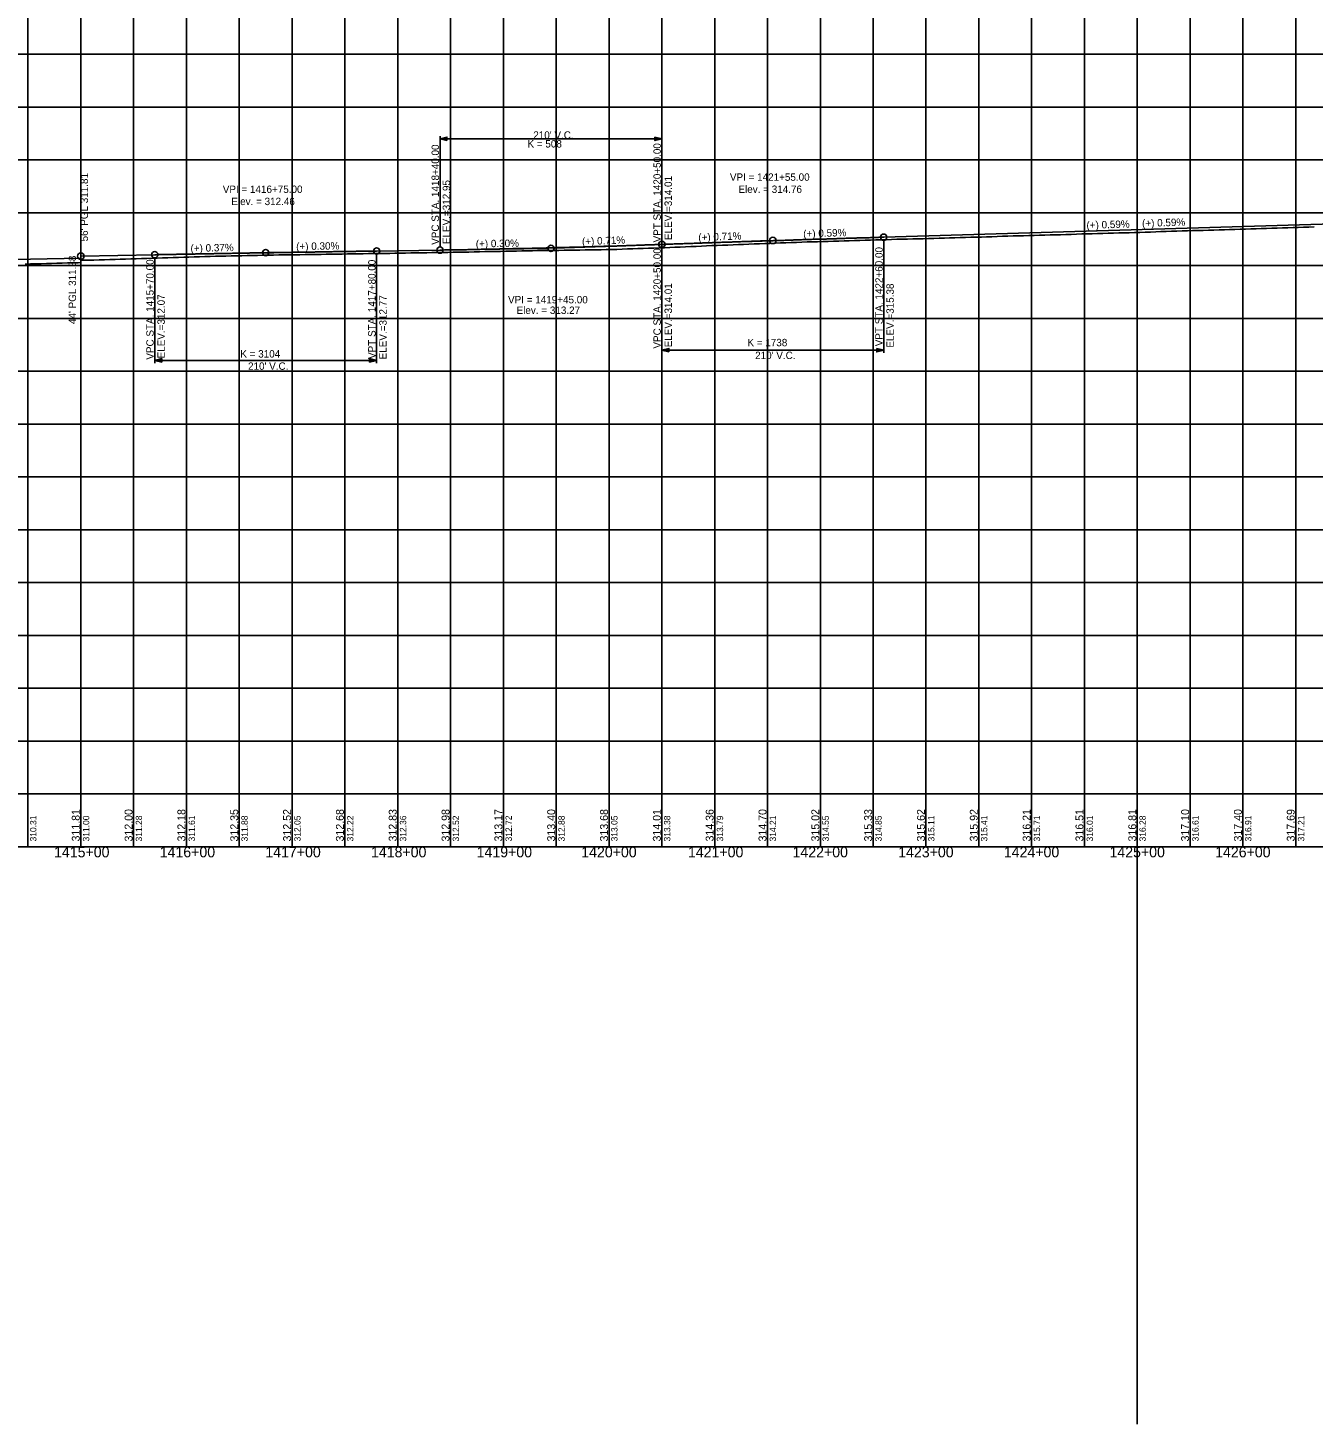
# Model space of a CAD drawing. Extents: x -90830 to 2015517, y -20856 to 836331.
# Drawn here: x 30373 to 31590, y -11344 to -10022 of the extents above; entities that cross this region are included whole.
import ezdxf

# ---------------------------------------------------------------- set-up
doc = ezdxf.new("R2010")
doc.units = 0
for name, color, linetype in [('Level 1', 7, 'Continuous'), ('RD_DDB_GradeTX', 7, 'Continuous'), ('RD_DDB_Profile_Elev', 7, 'Continuous'), ('RD_DDB_Profile_EX', 7, 'Continuous'), ('RD_DDB_Profile_Lbl', 7, 'Continuous'), ('RD_DDB_Profile_PR', 7, 'Continuous'), ('RD_DDB_StaTX', 7, 'Continuous'), ('RD_DDB_StripGrade', 7, 'Continuous'), ('RD_DDB_VCLbl', 7, 'Continuous'), ('RD_GPK_Profile_Cell', 7, 'Continuous'), ('RD_TX_Drainage', 7, 'Continuous')]:
    doc.layers.add(name, color=color, linetype=linetype)

msp = doc.modelspace()

# ---------------------------------------------------------------- linework, layer by layer
at = {"layer": 'Level 1'}
for p, q in [((31423.5, -3180.8), (31423.5, -11343.5)), ((30373.5, -9797.1), (30373.5, -10297.1)), ((30373.5, -9797.1), (30373.5, -10297.1)), ((30373.5, -9797.1), (30373.5, -10297.1)), ((30423.5, -9797.1), (30423.5, -10297.1)), ((30473.5, -9797.1), (30473.5, -10297.1)), ((30523.5, -9797.1), (30523.5, -10297.1)), ((30573.5, -9797.1), (30573.5, -10297.1)), ((30623.5, -9797.1), (30623.5, -10297.1)), ((30673.5, -9797.1), (30673.5, -10297.1)), ((30723.5, -9797.1), (30723.5, -10297.1)), ((30773.5, -9797.1), (30773.5, -10297.1)), ((30823.5, -9797.1), (30823.5, -10297.1)), ((30873.5, -9797.1), (30873.5, -10297.1)), ((30923.5, -9797.1), (30923.5, -10297.1)), ((30973.5, -9797.1), (30973.5, -10297.1)), ((31023.5, -9797.1), (31023.5, -10297.1)), ((31073.5, -9797.1), (31073.5, -10297.1)), ((31123.5, -9797.1), (31123.5, -10297.1)), ((31173.5, -9797.1), (31173.5, -10297.1)), ((31223.5, -9797.1), (31223.5, -10297.1)), ((31273.5, -9797.1), (31273.5, -10297.1)), ((31323.5, -9797.1), (31323.5, -10297.1)), ((31373.5, -9797.1), (31373.5, -10297.1)), ((31423.5, -9797.1), (31423.5, -10297.1)), ((31473.5, -9797.1), (31473.5, -10297.1)), ((31523.5, -9797.1), (31523.5, -10297.1)), ((31573.5, -9797.1), (31573.5, -10297.1)), ((28773.5, -10047.1), (30373.5, -10047.1)), ((30373.5, -10047.1), (31973.5, -10047.1)), ((28773.5, -10097.1), (30373.5, -10097.1)), ((30373.5, -10097.1), (31973.5, -10097.1)), ((28773.5, -10147.1), (30373.5, -10147.1)), ((30373.5, -10147.1), (31973.5, -10147.1)), ((28773.5, -10197.1), (30373.5, -10197.1)), ((30373.5, -10197.1), (31973.5, -10197.1)), ((28773.5, -10247.1), (30373.5, -10247.1)), ((30373.5, -10247.1), (31973.5, -10247.1)), ((28773.5, -10297.1), (30373.5, -10297.1)), ((28773.5, -10297.1), (30373.5, -10297.1)), ((30373.5, -10297.1), (30373.5, -10797.1)), ((30373.5, -10297.1), (30373.5, -10797.1)), ((30373.5, -10297.1), (31973.5, -10297.1)), ((30373.5, -10297.1), (31973.5, -10297.1)), ((30373.5, -10297.1), (30373.5, -10797.1)), ((30423.5, -10297.1), (30423.5, -10797.1)), ((30473.5, -10297.1), (30473.5, -10797.1)), ((30523.5, -10297.1), (30523.5, -10797.1)), ((30573.5, -10297.1), (30573.5, -10797.1)), ((30623.5, -10297.1), (30623.5, -10797.1)), ((30673.5, -10297.1), (30673.5, -10797.1)), ((30723.5, -10297.1), (30723.5, -10797.1)), ((30773.5, -10297.1), (30773.5, -10797.1)), ((30823.5, -10297.1), (30823.5, -10797.1)), ((30873.5, -10297.1), (30873.5, -10797.1)), ((30923.5, -10297.1), (30923.5, -10797.1)), ((30973.5, -10297.1), (30973.5, -10797.1)), ((31023.5, -10297.1), (31023.5, -10797.1)), ((31073.5, -10297.1), (31073.5, -10797.1)), ((31123.5, -10297.1), (31123.5, -10797.1)), ((31173.5, -10297.1), (31173.5, -10797.1)), ((31223.5, -10297.1), (31223.5, -10797.1)), ((31273.5, -10297.1), (31273.5, -10797.1)), ((31323.5, -10297.1), (31323.5, -10797.1)), ((31373.5, -10297.1), (31373.5, -10797.1)), ((31423.5, -10297.1), (31423.5, -10797.1)), ((31473.5, -10297.1), (31473.5, -10797.1)), ((31523.5, -10297.1), (31523.5, -10797.1)), ((31573.5, -10297.1), (31573.5, -10797.1)), ((28773.5, -10347.1), (30373.5, -10347.1)), ((30373.5, -10347.1), (31973.5, -10347.1)), ((28773.5, -10397.1), (30373.5, -10397.1)), ((30373.5, -10397.1), (31973.5, -10397.1)), ((28773.5, -10447.1), (30373.5, -10447.1)), ((30373.5, -10447.1), (31973.5, -10447.1)), ((28773.5, -10497.1), (30373.5, -10497.1)), ((30373.5, -10497.1), (31973.5, -10497.1)), ((28773.5, -10547.1), (30373.5, -10547.1)), ((30373.5, -10547.1), (31973.5, -10547.1)), ((28773.5, -10597.1), (30373.5, -10597.1)), ((30373.5, -10597.1), (31973.5, -10597.1)), ((28773.5, -10647.1), (30373.5, -10647.1)), ((30373.5, -10647.1), (31973.5, -10647.1)), ((28773.5, -10697.1), (30373.5, -10697.1)), ((30373.5, -10697.1), (31973.5, -10697.1)), ((28773.5, -10747.1), (30373.5, -10747.1)), ((30373.5, -10747.1), (31973.5, -10747.1)), ((28773.5, -10797.1), (30373.5, -10797.1)), ((30373.5, -10797.1), (31973.5, -10797.1))]:
    msp.add_line(p, q, dxfattribs=at)
at = {"layer": 'RD_DDB_GradeTX'}
for p, q in [((31007.5, -10225.8), (31075.5, -10223.4)), ((31149.4, -10221.2), (31081.5, -10223.2)), ((30527.5, -10236.1), (30595.5, -10234.9)), ((30669.5, -10233.8), (30601.5, -10234.8)), ((30797.5, -10231.9), (30865.5, -10230.8)), ((30939.4, -10228.3), (30871.5, -10230.7))]:
    msp.add_line(p, q, dxfattribs=at)
for centre in [(31078.5, -10223.3), (30423.5, -10238.1), (30598.5, -10234.8), (30868.5, -10230.8)]:
    msp.add_circle(centre, 3, dxfattribs=at)
at = {"layer": 'RD_DDB_Profile_EX'}
for points in [[(31420.9, -10215.8), (31425.9, -10215.6), (31430.9, -10215.5), (31435.9, -10215.3), (31440.9, -10215.1), (31445.9, -10214.9), (31450.9, -10214.8), (31455.9, -10214.6), (31460.9, -10214.4), (31465.9, -10214.3), (31470.9, -10214.1), (31475.9, -10214), (31480.9, -10213.9), (31485.9, -10213.7), (31490.9, -10213.6), (31495.9, -10213.4), (31500.9, -10213.3), (31505.9, -10213.1), (31510.9, -10213), (31515.9, -10212.8), (31520.9, -10212.7), (31525.9, -10212.5), (31530.9, -10212.3), (31535.9, -10212.2), (31540.9, -10212), (31545.9, -10211.8), (31550.9, -10211.6), (31555.9, -10211.5), (31560.9, -10211.4), (31565.9, -10211.3), (31570.9, -10211.1), (31575.9, -10211), (31580.9, -10210.8), (31585.9, -10210.7), (31590.9, -10210.5)], [(30920.9, -10231.9), (30925.9, -10231.8), (30930.9, -10231.7), (30935.9, -10231.5), (30940.9, -10231.3), (30945.9, -10231.2), (30950.9, -10231), (30955.9, -10230.9), (30960.9, -10230.7), (30965.9, -10230.5), (30970.9, -10230.3), (30975.9, -10230.1), (30980.9, -10229.9), (30985.9, -10229.7), (30990.9, -10229.5), (30995.9, -10229.3), (31000.9, -10229.1), (31005.9, -10228.9), (31010.9, -10228.7), (31015.9, -10228.5), (31020.9, -10228.2), (31025.9, -10228), (31030.9, -10227.8), (31035.9, -10227.6), (31040.9, -10227.4), (31045.9, -10227.2), (31050.9, -10227), (31055.9, -10226.8), (31060.9, -10226.6), (31065.9, -10226.4), (31070.9, -10226.2), (31075.9, -10226), (31080.9, -10225.8), (31085.9, -10225.6), (31090.9, -10225.4), (31095.9, -10225.2), (31100.9, -10225.1), (31105.9, -10224.9), (31110.9, -10224.7), (31115.9, -10224.6), (31120.9, -10224.5), (31125.9, -10224.3), (31130.9, -10224.2), (31135.9, -10224), (31140.9, -10223.9), (31145.9, -10223.7), (31150.9, -10223.6), (31155.9, -10223.4), (31160.9, -10223.2), (31165.9, -10223.1), (31170.9, -10222.9), (31175.9, -10222.8), (31180.9, -10222.7), (31185.9, -10222.6), (31190.9, -10222.4), (31195.9, -10222.2), (31200.9, -10222.1), (31205.9, -10221.9), (31210.9, -10221.8), (31215.9, -10221.7), (31220.9, -10221.6), (31225.9, -10221.5), (31230.9, -10221.4), (31235.9, -10221.2), (31240.9, -10221), (31245.9, -10220.9), (31250.9, -10220.7), (31255.9, -10220.6), (31260.9, -10220.4), (31265.9, -10220.3), (31270.9, -10220.2), (31275.9, -10220), (31280.9, -10219.8), (31285.9, -10219.7), (31290.9, -10219.5), (31295.9, -10219.3), (31300.9, -10219.2), (31305.9, -10219), (31310.9, -10218.9), (31315.9, -10218.8), (31320.9, -10218.7), (31325.9, -10218.5), (31330.9, -10218.4), (31335.9, -10218.3), (31340.9, -10218.1), (31345.9, -10218), (31350.9, -10217.8), (31355.9, -10217.6), (31360.9, -10217.5), (31365.9, -10217.3), (31370.9, -10217.1), (31375.9, -10217), (31380.9, -10216.9), (31385.9, -10216.7), (31390.9, -10216.6), (31395.9, -10216.5), (31400.9, -10216.4), (31405.9, -10216.2), (31410.9, -10216.1), (31415.9, -10215.9), (31420.9, -10215.8)], [(30423.5, -10242.1), (30425.9, -10242), (30430.9, -10241.9), (30435.9, -10241.8), (30440.9, -10241.6), (30445.9, -10241.5), (30450.9, -10241.3), (30455.9, -10241.2), (30460.9, -10241.1), (30465.9, -10240.9), (30470.9, -10240.8), (30475.9, -10240.6), (30480.9, -10240.5), (30485.9, -10240.3), (30490.9, -10240.1), (30495.9, -10240), (30500.9, -10239.8), (30505.9, -10239.6), (30510.9, -10239.5), (30515.9, -10239.3), (30520.9, -10239.1), (30525.9, -10239), (30530.9, -10238.8), (30535.9, -10238.7), (30540.9, -10238.5), (30545.9, -10238.3), (30550.9, -10238.2), (30555.9, -10238.1), (30560.9, -10238), (30565.9, -10237.9), (30570.9, -10237.8), (30575.9, -10237.7), (30580.9, -10237.6), (30585.9, -10237.5), (30590.9, -10237.4), (30595.9, -10237.3), (30600.9, -10237.2), (30605.9, -10237.1), (30610.9, -10237), (30615.9, -10237), (30620.9, -10236.9), (30625.9, -10236.8), (30630.9, -10236.8), (30635.9, -10236.7), (30640.9, -10236.6), (30645.9, -10236.5), (30650.9, -10236.5), (30655.9, -10236.4), (30660.9, -10236.3), (30665.9, -10236.2), (30670.9, -10236.1), (30675.9, -10236), (30680.9, -10235.9), (30685.9, -10235.9), (30690.9, -10235.8), (30695.9, -10235.7), (30700.9, -10235.7), (30705.9, -10235.6), (30710.9, -10235.5), (30715.9, -10235.5), (30720.9, -10235.4), (30725.9, -10235.3), (30730.9, -10235.2), (30735.9, -10235.1), (30740.9, -10235), (30745.9, -10234.9), (30750.9, -10234.9), (30755.9, -10234.8), (30760.9, -10234.7), (30765.9, -10234.6), (30770.9, -10234.6), (30775.9, -10234.5), (30780.9, -10234.4), (30785.9, -10234.3), (30790.9, -10234.2), (30795.9, -10234.1), (30800.9, -10234), (30805.9, -10233.8), (30810.9, -10233.7), (30815.9, -10233.6), (30820.9, -10233.6), (30825.9, -10233.5), (30830.9, -10233.4), (30835.9, -10233.3), (30840.9, -10233.1), (30845.9, -10233), (30850.9, -10233), (30855.9, -10232.9), (30860.9, -10232.9), (30865.9, -10232.8), (30870.9, -10232.8), (30875.9, -10232.7), (30880.9, -10232.6), (30885.9, -10232.6), (30890.9, -10232.5), (30895.9, -10232.4), (30900.9, -10232.3), (30905.9, -10232.2), (30910.9, -10232.1), (30915.9, -10232), (30920.9, -10231.9)], [(30370.9, -10245.6), (30375.9, -10245.5), (30380.9, -10245.4), (30385.9, -10245.3), (30390.9, -10245.2), (30395.9, -10245), (30400.9, -10244.9), (30405.9, -10244.7), (30410.9, -10244.6), (30415.9, -10244.5), (30420.9, -10244.3), (30423.5, -10244.2)]]:
    msp.add_lwpolyline(points, dxfattribs=at)
at = {"layer": 'RD_DDB_Profile_PR'}
for p, q in [((31183.5, -10220.2), (32143.5, -10191.8)), ((30188.5, -10244.3), (30423.4, -10240)), ((30423.5, -10238.1), (30493.5, -10236.8)), ((30703.5, -10233.3), (30763.5, -10232.4))]:
    msp.add_line(p, q, dxfattribs=at)
for points in [[(30763.5, -10232.4), (30767.7, -10232.3), (30771.9, -10232.2), (30776.1, -10232.2), (30780.3, -10232.1), (30784.5, -10232), (30788.7, -10232), (30792.9, -10231.9), (30797.1, -10231.8), (30801.3, -10231.7), (30805.5, -10231.6), (30809.7, -10231.6), (30813.9, -10231.5), (30818.1, -10231.4), (30822.3, -10231.3), (30826.5, -10231.2), (30830.7, -10231.1), (30834.9, -10231), (30839.1, -10231), (30843.3, -10230.9), (30847.5, -10230.8), (30851.7, -10230.7), (30855.9, -10230.6), (30860.1, -10230.5), (30864.3, -10230.4), (30868.5, -10230.2), (30872.7, -10230.1), (30876.9, -10230), (30881.1, -10229.9), (30885.3, -10229.8), (30889.5, -10229.7), (30893.7, -10229.6), (30897.9, -10229.5), (30902.1, -10229.3), (30906.3, -10229.2), (30910.5, -10229.1), (30914.7, -10229), (30918.9, -10228.8), (30923.1, -10228.7), (30927.3, -10228.6), (30931.5, -10228.5), (30935.7, -10228.3), (30939.9, -10228.2), (30944.1, -10228.1), (30948.3, -10227.9), (30952.5, -10227.8), (30956.7, -10227.6), (30960.9, -10227.5), (30965.1, -10227.3), (30969.3, -10227.2), (30973.5, -10227)], [(30973.5, -10227), (30977.7, -10226.9), (30981.9, -10226.7), (30986.1, -10226.6), (30990.3, -10226.5), (30994.5, -10226.3), (30998.7, -10226.2), (31002.9, -10226), (31007.1, -10225.9), (31011.3, -10225.7), (31015.5, -10225.6), (31019.7, -10225.4), (31023.9, -10225.3), (31028.1, -10225.1), (31032.3, -10225), (31036.5, -10224.9), (31040.7, -10224.7), (31044.9, -10224.6), (31049.1, -10224.4), (31053.3, -10224.3), (31057.5, -10224.2), (31061.7, -10224), (31065.9, -10223.9), (31070.1, -10223.7), (31074.3, -10223.6), (31078.5, -10223.5), (31082.7, -10223.3), (31086.9, -10223.2), (31091.1, -10223.1), (31095.3, -10222.9), (31099.5, -10222.8), (31103.7, -10222.6), (31107.9, -10222.5), (31112.1, -10222.4), (31116.3, -10222.2), (31120.5, -10222.1), (31124.7, -10222), (31128.9, -10221.9), (31133.1, -10221.7), (31137.3, -10221.6), (31141.5, -10221.5), (31145.7, -10221.3), (31149.9, -10221.2), (31154.1, -10221.1), (31158.3, -10220.9), (31162.5, -10220.8), (31166.7, -10220.7), (31170.9, -10220.6), (31175.1, -10220.4), (31179.3, -10220.3), (31183.5, -10220.2)], [(30493.5, -10236.8), (30497.7, -10236.7), (30501.9, -10236.6), (30506.1, -10236.5), (30510.3, -10236.5), (30514.5, -10236.4), (30518.7, -10236.3), (30522.9, -10236.2), (30527.1, -10236.2), (30531.3, -10236.1), (30535.5, -10236), (30539.7, -10235.9), (30543.9, -10235.9), (30548.1, -10235.8), (30552.3, -10235.7), (30556.5, -10235.6), (30560.7, -10235.6), (30564.9, -10235.5), (30569.1, -10235.4), (30573.3, -10235.4), (30577.5, -10235.3), (30581.7, -10235.2), (30585.9, -10235.1), (30590.1, -10235.1), (30594.3, -10235), (30598.5, -10234.9), (30602.7, -10234.9), (30606.9, -10234.8), (30611.1, -10234.7), (30615.3, -10234.7), (30619.5, -10234.6), (30623.7, -10234.5), (30627.9, -10234.4), (30632.1, -10234.4), (30636.3, -10234.3), (30640.5, -10234.2), (30644.7, -10234.2), (30648.9, -10234.1), (30653.1, -10234), (30657.3, -10234), (30661.5, -10233.9), (30665.7, -10233.8), (30669.9, -10233.8), (30674.1, -10233.7), (30678.3, -10233.6), (30682.5, -10233.6), (30686.7, -10233.5), (30690.9, -10233.5), (30695.1, -10233.4), (30699.3, -10233.3), (30703.5, -10233.3)]]:
    msp.add_spline(points, degree=3, dxfattribs=at)
at = {"layer": 'RD_DDB_VCLbl'}
for p, q in [((30763.5, -10124.5), (30763.5, -10229.4)), ((30763.5, -10127), (30973.5, -10127)), ((30973.5, -10124.5), (30973.5, -10224)), ((31183.5, -10329.5), (31183.5, -10223.2)), ((30493.5, -10339.3), (30493.5, -10239.8)), ((30703.5, -10339.3), (30703.5, -10236.3)), ((30973.5, -10329.5), (30973.5, -10230)), ((30973.5, -10327), (31183.5, -10327)), ((30493.5, -10336.8), (30703.5, -10336.8))]:
    msp.add_line(p, q, dxfattribs=at)
for centre in [(30973.5, -10227), (31183.5, -10220.2), (30493.5, -10236.8), (30703.5, -10233.3), (30763.5, -10232.4)]:
    msp.add_circle(centre, 3, dxfattribs=at)
at = {"layer": 'RD_GPK_Profile_Cell'}
msp.add_line((4823.5, -10797.1), (75223.5, -10797.1), dxfattribs=at)
at = {"layer": 'RD_TX_Drainage'}
for points in [[(30770.1, -10128.7), (30763.5, -10127), (30770.1, -10125.4)], [(30966.9, -10125.4), (30973.5, -10127), (30966.9, -10128.7)], [(30980.1, -10328.7), (30973.5, -10327), (30980.1, -10325.4)], [(31176.9, -10325.4), (31183.5, -10327), (31176.9, -10328.7)], [(30500.1, -10338.4), (30493.5, -10336.8), (30500.1, -10335.1)], [(30696.9, -10335.1), (30703.5, -10336.8), (30696.9, -10338.4)]]:
    msp.add_lwpolyline(points, close=True, dxfattribs=at)

# ---------------------------------------------------------------- texts
at = {"layer": 'RD_DDB_GradeTX'}
for s, rotation, p in [('(+) 0.59%', 1.6963, (31107.4, -10220.4)), ('(+) 0.59%', 1.6963, (31375.5, -10212.3)), ('(+) 0.59%', 1.6963, (31428.1, -10210.5)), ('(+) 0.37%', 1.0532, (30527.4, -10234.1)), ('(+) 0.30%', 0.8594, (30627.4, -10232.4)), ('(+) 0.30%', 0.8594, (30797.4, -10229.9)), ('(+) 0.71%', 2.0421, (30898, -10227.7)), ('(+) 0.71%', 2.0421, (31008.1, -10223.8))]:
    msp.add_text(s, height=7, rotation=rotation, dxfattribs=at).set_placement(p)
at = {"layer": 'RD_DDB_Profile_Elev'}
for s, p in [('311.81', (30422.5, -10792.1)), ('312.00', (30472.5, -10792.1)), ('312.18', (30522.5, -10792.1)), ('312.35', (30572.5, -10792.1)), ('312.52', (30622.5, -10792.1)), ('312.68', (30672.5, -10792.1)), ('312.83', (30722.5, -10792.1)), ('312.98', (30772.5, -10792.1)), ('313.17', (30822.5, -10792.1)), ('313.40', (30872.5, -10792.1)), ('313.68', (30922.5, -10792.1)), ('314.01', (30972.5, -10792.1)), ('314.36', (31022.5, -10792.1)), ('314.70', (31072.5, -10792.1)), ('315.02', (31122.5, -10792.1)), ('315.33', (31172.5, -10792.1)), ('315.62', (31222.5, -10792.1)), ('315.92', (31272.5, -10792.1)), ('316.21', (31322.5, -10792.1)), ('316.51', (31372.5, -10792.1)), ('316.81', (31422.5, -10792.1)), ('317.10', (31472.5, -10792.1)), ('317.40', (31522.5, -10792.1)), ('317.69', (31572.5, -10792.1))]:
    msp.add_text(s, height=7.5, rotation=90, dxfattribs=at).set_placement(p)
at = {"layer": 'RD_DDB_Profile_Lbl'}
for s, p in [("56' PGL 311.81", (30430.3, -10224.2)), ("44' PGL 311.38", (30419, -10302.4))]:
    msp.add_text(s, height=7, rotation=90, dxfattribs=at).set_placement(p)
for s, p in [('VPI = 1421+55.00', (31037.9, -10166.8)), ('VPI = 1416+75.00', (30557.9, -10178.3)), ('Elev. = 314.76', (31046, -10178.3)), ('Elev. = 312.46', (30566, -10189.8)), ('VPI = 1419+45.00', (30827.9, -10282.8)), ('Elev. = 313.27', (30836, -10292.8))]:
    msp.add_text(s, height=7, dxfattribs=at).set_placement(p)
at = {"layer": 'RD_DDB_StaTX'}
for s, p in [('1415+00', (30398.2, -10807.1)), ('1416+00', (30498.2, -10807.1)), ('1417+00', (30598.2, -10807.1)), ('1418+00', (30698.2, -10807.1)), ('1419+00', (30798.2, -10807.1)), ('1420+00', (30897.2, -10807.1)), ('1421+00', (30998.2, -10807.1)), ('1422+00', (31097.2, -10807.1)), ('1423+00', (31197.2, -10807.1)), ('1424+00', (31297.2, -10807.1)), ('1425+00', (31397.2, -10807.1)), ('1426+00', (31497.2, -10807.1))]:
    msp.add_text(s, height=10, dxfattribs=at).set_placement(p)
at = {"layer": 'RD_DDB_StripGrade'}
for s, height, p in [('VPC STA. 1418+40.00 ', 7, (30762.5, -10227.4)), ('VPT STA. 1420+50.00 ', 7, (30972.5, -10225.1)), ('ELEV.=312.95', 7, (30773, -10226.7)), ('ELEV.=314.01', 7, (30983, -10222.9)), ('VPC STA. 1420+50.00 ', 7, (30972.5, -10325.6)), ('VPT STA. 1422+60.00 ', 7, (31182.5, -10323.4)), ('VPC STA. 1415+70.00 ', 7, (30492.5, -10336.1)), ('VPT STA. 1417+80.00 ', 7, (30702.5, -10335.4)), ('ELEV.=314.01', 7, (30983, -10324.4)), ('ELEV.=315.38', 7, (31193, -10324.7)), ('ELEV.=312.07', 7, (30503, -10334.9)), ('ELEV.=312.77', 7, (30713, -10335.8)), ('310.31', 6, (30381.5, -10792.1)), ('311.00', 6, (30431.5, -10792.1)), ('311.28', 6, (30481.5, -10792.1)), ('311.61', 6, (30531.5, -10792.1)), ('311.88', 6, (30581.5, -10792.1)), ('312.05', 6, (30631.5, -10792.1)), ('312.22', 6, (30681.5, -10792.1)), ('312.36', 6, (30731.5, -10792.1)), ('312.52', 6, (30781.5, -10792.1)), ('312.72', 6, (30831.5, -10792.1)), ('312.88', 6, (30881.5, -10792.1)), ('313.05', 6, (30931.5, -10792.1)), ('313.38', 6, (30981.5, -10792.1)), ('313.79', 6, (31031.5, -10792.1)), ('314.21', 6, (31081.5, -10792.1)), ('314.55', 6, (31131.5, -10792.1)), ('314.85', 6, (31181.5, -10792.1)), ('315.11', 6, (31231.5, -10792.1)), ('315.41', 6, (31281.5, -10792.1)), ('315.71', 6, (31331.5, -10792.1)), ('316.01', 6, (31381.5, -10792.1)), ('316.28', 6, (31431.5, -10792.1)), ('316.61', 6, (31481.5, -10792.1)), ('316.91', 6, (31531.5, -10792.1)), ('317.21', 6, (31581.5, -10792.1))]:
    msp.add_text(s, height=height, rotation=90, dxfattribs=at).set_placement(p)
at = {"layer": 'RD_DDB_VCLbl'}
for s, p in [("210' V.C.", (30851.8, -10127)), ('K = 508', (30846.3, -10135.3)), ('K = 1738', (31054.5, -10323.4)), ('K = 3104', (30574.5, -10334.1)), ("210' V.C.", (31061.8, -10335.5)), ("210' V.C.", (30581.8, -10345.7))]:
    msp.add_text(s, height=7, dxfattribs=at).set_placement(p)

doc.saveas('drawing.dxf')
